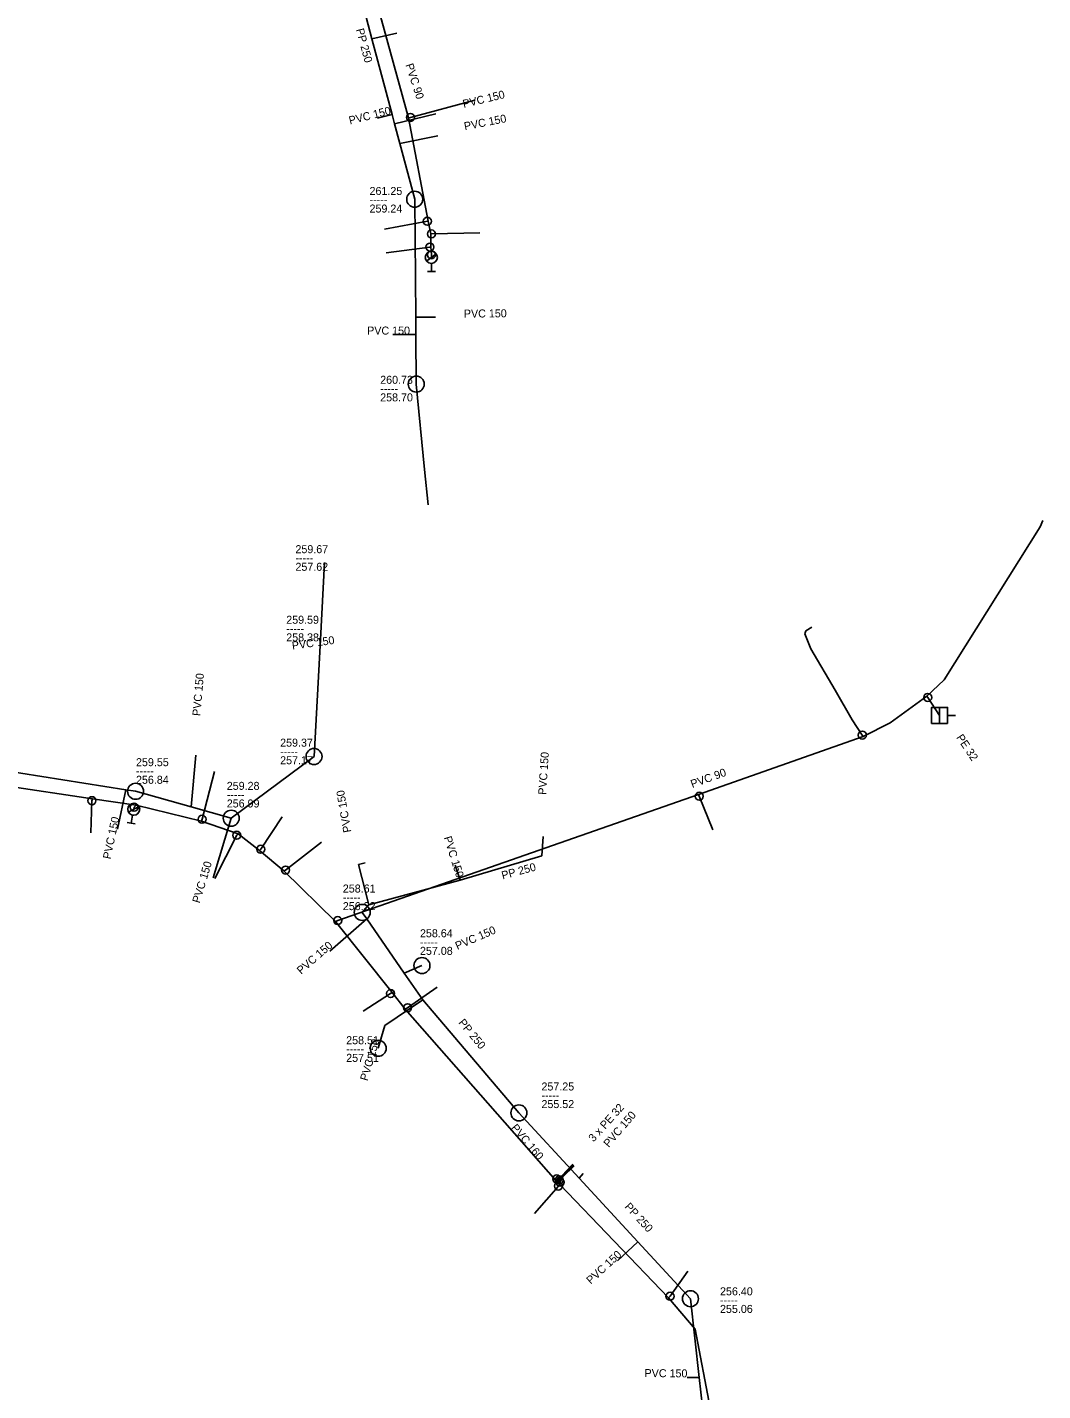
# Model space of a CAD drawing. Extents: x -770828 to -770111, y -1050344 to -1049447.
# Drawn here: x -770523.9 to -770397, y -1050086.5 to -1049916.1 of the extents above; entities that cross this region are included whole.
import ezdxf

# ---------------------------------------------------------------- set-up
doc = ezdxf.new("R2010")
doc.units = 0
doc.layers.add('Level 0', color=7, linetype='Continuous')

msp = doc.modelspace()

# ---------------------------------------------------------------- linework, layer by layer
at = {"layer": 'Level 0'}
for p, q in [((-770484.57, -1049903.39), (-770480.8, -1049917.54)), ((-770479.95, -1049913.96), (-770476.22, -1049927.41)), ((-770480.8, -1049917.54), (-770477.68, -1049916.84)), ((-770480.8, -1049917.54), (-770478.28, -1049926.99)), ((-770476, -1049927.35), (-770467.95, -1049925.2)), ((-770478.28, -1049926.99), (-770480.12, -1049927.45)), ((-770478.28, -1049926.99), (-770477.97, -1049928.16)), ((-770477.97, -1049928.16), (-770472.82, -1049926.92)), ((-770477.97, -1049928.16), (-770477.32, -1049930.6)), ((-770476.22, -1049927.41), (-770476, -1049927.35)), ((-770476.22, -1049927.41), (-770473.78, -1049940.31)), ((-770477.32, -1049930.6), (-770472.58, -1049929.67)), ((-770477.32, -1049930.6), (-770475.46, -1049937.58)), ((-770475.46, -1049937.58), (-770475.33, -1049952.33)), ((-770473.88, -1049940.33), (-770479.24, -1049941.32)), ((-770473.78, -1049940.31), (-770473.88, -1049940.33)), ((-770473.78, -1049940.31), (-770473.46, -1049941.91)), ((-770473.36, -1049941.91), (-770467.3, -1049941.76)), ((-770473.55, -1049943.55), (-770479.04, -1049944.26)), ((-770473.45, -1049943.54), (-770473.55, -1049943.55)), ((-770473.46, -1049941.91), (-770473.36, -1049941.91)), ((-770473.46, -1049941.91), (-770473.45, -1049943.54)), ((-770473.45, -1049943.54), (-770473.37, -1049944.52)), ((-770472.79, -1049944.38), (-770473.97, -1049945.3)), ((-770473.37, -1049944.52), (-770473.38, -1049944.84)), ((-770472.88, -1049946.59), (-770473.88, -1049946.59)), ((-770473.38, -1049945.59), (-770473.38, -1049946.59)), ((-770475.33, -1049952.33), (-770472.88, -1049952.31)), ((-770475.33, -1049952.33), (-770475.31, -1049954.49)), ((-770475.31, -1049954.49), (-770478.18, -1049954.48)), ((-770475.31, -1049954.49), (-770475.26, -1049960.68)), ((-770475.26, -1049960.68), (-770474.22, -1049971.34)), ((-770474.22, -1049971.34), (-770473.78, -1049975.77)), ((-770409.32, -1049997.65), (-770397.32, -1049978.5)), ((-770397.32, -1049978.5), (-770396.99, -1049977.74)), ((-770486.71, -1049982.98), (-770487.24, -1049992.58)), ((-770426.57, -1049991.52), (-770425.85, -1049991.06)), ((-770487.24, -1049992.58), (-770488.04, -1050007.22)), ((-770426.7, -1049991.91), (-770426.57, -1049991.52)), ((-770425.98, -1049993.75), (-770426.7, -1049991.91)), ((-770422.94, -1049998.93), (-770425.98, -1049993.75)), ((-770411.47, -1049999.68), (-770409.32, -1049997.65)), ((-770420.8, -1050002.64), (-770422.94, -1049998.93)), ((-770416.05, -1050003.03), (-770411.47, -1049999.68)), ((-770411.47, -1049999.68), (-770411.36, -1049999.84)), ((-770411.36, -1049999.84), (-770409.88, -1050002.09)), ((-770419.53, -1050004.55), (-770420.8, -1050002.64)), ((-770419.42, -1050004.71), (-770416.05, -1050003.03)), ((-770407.88, -1050002.09), (-770408.88, -1050002.09)), ((-770439.99, -1050011.95), (-770419.42, -1050004.71)), ((-770419.42, -1050004.71), (-770419.53, -1050004.55)), ((-770503.39, -1050013.52), (-770502.82, -1050007.04)), ((-770488.04, -1050007.22), (-770498.38, -1050014.93)), ((-770511.54, -1050011.38), (-770527.35, -1050008.9)), ((-770502.02, -1050015.07), (-770500.48, -1050009.1)), ((-770515.73, -1050012.51), (-770526.84, -1050010.84)), ((-770511.54, -1050011.38), (-770512.58, -1050016.3)), ((-770510.33, -1050011.57), (-770511.54, -1050011.38)), ((-770503.39, -1050013.52), (-770510.33, -1050011.57)), ((-770515.79, -1050012.74), (-770515.93, -1050016.74)), ((-770515.73, -1050012.51), (-770515.79, -1050012.74)), ((-770510.25, -1050013.31), (-770515.73, -1050012.51)), ((-770510.25, -1050013.31), (-770510.51, -1050013.57)), ((-770502.11, -1050015.29), (-770510.25, -1050013.31)), ((-770485.07, -1050027.72), (-770439.99, -1050011.95)), ((-770439.99, -1050011.95), (-770439.9, -1050012.18)), ((-770439.9, -1050012.18), (-770438.22, -1050016.37)), ((-770509.91, -1050013.47), (-770511.23, -1050014.17)), ((-770510.7, -1050014.56), (-770510.87, -1050015.54)), ((-770510.51, -1050013.57), (-770510.57, -1050013.82)), ((-770498.38, -1050014.93), (-770503.39, -1050013.52)), ((-770502.11, -1050015.29), (-770502.02, -1050015.07)), ((-770498.38, -1050014.93), (-770500.64, -1050022.4)), ((-770494.7, -1050018.81), (-770492.01, -1050014.75)), ((-770510.38, -1050015.63), (-770511.37, -1050015.46)), ((-770497.52, -1050016.87), (-770502.11, -1050015.29)), ((-770497.52, -1050016.87), (-770497.69, -1050017.06)), ((-770494.87, -1050018.98), (-770497.52, -1050016.87)), ((-770497.69, -1050017.06), (-770500.44, -1050022.47)), ((-770491.59, -1050021.41), (-770487.11, -1050017.91)), ((-770459.58, -1050019.64), (-770459.42, -1050017.2)), ((-770494.87, -1050018.98), (-770494.7, -1050018.81)), ((-770491.81, -1050021.52), (-770494.87, -1050018.98)), ((-770459.58, -1050019.64), (-770469.79, -1050022.69)), ((-770491.81, -1050021.52), (-770491.59, -1050021.41)), ((-770485.35, -1050027.84), (-770491.81, -1050021.52)), ((-770482.46, -1050020.71), (-770481.65, -1050020.53)), ((-770481.2, -1050025.77), (-770482.46, -1050020.71)), ((-770469.79, -1050022.69), (-770470.39, -1050020.79)), ((-770469.79, -1050022.69), (-770481.2, -1050025.77)), ((-770481.2, -1050025.77), (-770482.01, -1050026.7)), ((-770482.01, -1050026.7), (-770481.45, -1050027.51)), ((-770481.45, -1050027.51), (-770486.07, -1050031.56)), ((-770485.35, -1050027.84), (-770485.07, -1050027.72)), ((-770478.29, -1050036.71), (-770485.35, -1050027.84)), ((-770481.45, -1050027.51), (-770476.76, -1050034.31)), ((-770476.76, -1050034.31), (-770474.55, -1050033.35)), ((-770476.76, -1050034.31), (-770474.43, -1050037.65)), ((-770478.48, -1050036.84), (-770481.88, -1050039.06)), ((-770478.29, -1050036.71), (-770478.48, -1050036.84)), ((-770476.63, -1050038.81), (-770478.29, -1050036.71)), ((-770476.35, -1050038.62), (-770472.67, -1050036.03)), ((-770474.43, -1050037.65), (-770479.17, -1050040.83)), ((-770476.63, -1050038.81), (-770476.35, -1050038.62)), ((-770457.82, -1050060.22), (-770476.63, -1050038.81)), ((-770474.43, -1050037.65), (-770462.44, -1050051.76)), ((-770479.17, -1050040.83), (-770480.02, -1050043.69)), ((-770462.44, -1050051.76), (-770454.92, -1050059.91)), ((-770455.72, -1050058.18), (-770457.1, -1050059.66)), ((-770457.03, -1050059.72), (-770455.62, -1050058.27)), ((-770455.52, -1050058.36), (-770456.98, -1050059.79)), ((-770454.92, -1050059.91), (-770454.42, -1050059.33)), ((-770457.5, -1050060.91), (-770460.5, -1050064.32)), ((-770457.71, -1050060.01), (-770457.82, -1050060.22)), ((-770457.67, -1050060.34), (-770457.82, -1050060.22)), ((-770457.1, -1050059.66), (-770457.71, -1050060.01)), ((-770457.67, -1050060.34), (-770457.4, -1050060.13)), ((-770457.47, -1050060.55), (-770457.67, -1050060.34)), ((-770457.32, -1050060.7), (-770457.5, -1050060.91)), ((-770457.29, -1050060.42), (-770457.47, -1050060.55)), ((-770457.32, -1050060.7), (-770457.47, -1050060.55)), ((-770457.4, -1050060.13), (-770457.03, -1050059.72)), ((-770443.76, -1050074.87), (-770457.32, -1050060.7)), ((-770456.98, -1050059.79), (-770457.29, -1050060.42)), ((-770454.92, -1050059.91), (-770447.56, -1050067.88)), ((-770447.56, -1050067.88), (-770450.11, -1050070.24)), ((-770447.56, -1050067.88), (-770441, -1050074.98)), ((-770443.56, -1050074.68), (-770441.32, -1050071.54)), ((-770443.76, -1050074.87), (-770443.56, -1050074.68)), ((-770440.42, -1050078.8), (-770443.76, -1050074.87)), ((-770441, -1050074.98), (-770439.91, -1050084.82)), ((-770438.53, -1050088.64), (-770440.42, -1050078.8)), ((-770439.91, -1050084.82), (-770441.4, -1050084.81)), ((-770439.91, -1050084.82), (-770439.09, -1050092.2))]:
    msp.add_line(p, q, dxfattribs=at)
msp.add_lwpolyline([(-770409.88, -1050003.09), (-770410.88, -1050003.09), (-770410.88, -1050001.09), (-770409.88, -1050001.09)], dxfattribs=at)
msp.add_lwpolyline([(-770408.88, -1050003.09), (-770408.88, -1050001.09), (-770409.88, -1050001.09), (-770409.88, -1050003.09)], close=True, dxfattribs=at)
for centre, radius in [((-770476, -1049927.35), 0.5), ((-770475.46, -1049937.58), 1), ((-770473.88, -1049940.33), 0.5), ((-770473.36, -1049941.91), 0.5), ((-770473.55, -1049943.55), 0.5), ((-770473.38, -1049944.84), 0.75), ((-770473.37, -1049944.52), 0.5), ((-770475.26, -1049960.68), 1), ((-770411.36, -1049999.84), 0.5), ((-770419.53, -1050004.55), 0.5), ((-770488.04, -1050007.22), 1), ((-770510.33, -1050011.57), 1), ((-770439.9, -1050012.18), 0.5), ((-770515.79, -1050012.74), 0.5), ((-770510.57, -1050013.82), 0.75), ((-770510.51, -1050013.57), 0.5), ((-770502.02, -1050015.07), 0.5), ((-770498.38, -1050014.93), 1), ((-770497.69, -1050017.06), 0.5), ((-770494.7, -1050018.81), 0.5), ((-770491.59, -1050021.41), 0.5), ((-770482.01, -1050026.7), 1), ((-770485.07, -1050027.72), 0.5), ((-770474.55, -1050033.35), 1), ((-770478.48, -1050036.84), 0.5), ((-770476.35, -1050038.62), 0.5), ((-770480.02, -1050043.69), 1), ((-770462.44, -1050051.76), 1), ((-770457.71, -1050060.01), 0.5), ((-770457.5, -1050060.91), 0.5), ((-770457.4, -1050060.13), 0.5), ((-770457.29, -1050060.42), 0.5), ((-770443.56, -1050074.68), 0.5), ((-770441, -1050074.98), 1)]:
    msp.add_circle(centre, radius, dxfattribs=at)

# ---------------------------------------------------------------- texts
for s, rotation, p in [('PP 250', 284.84, (-770482.8, -1049916.36)), ('PVC 90', 287.819, (-770476.62, -1049920.78)), ('PVC 150', 13.538, (-770469.33, -1049926.17)), ('PVC 150', 14.036, (-770483.55, -1049928.24)), ('PVC 150', 11.101, (-770469.19, -1049928.96)), ('PVC 150', 0.468, (-770469.31, -1049952.37)), ('PVC 150', 359.8, (-770481.4, -1049954.48)), ('PVC 150', 7.843, (-770490.73, -1049993.87)), ('PVC 150', 84.973, (-770502.25, -1050002.19)), ('PE 32', 303.336, (-770407.83, -1050004.84)), ('PVC 150', 86.248, (-770459.04, -1050012.03)), ('PVC 90', 20, (-770440.77, -1050011.17)), ('PVC 150', 99.837, (-770483.37, -1050016.64)), ('PVC 150', 78.064, (-770513.46, -1050020.11)), ('PVC 150', 287.526, (-770471.84, -1050017.35)), ('PVC 150', 73.167, (-770502.33, -1050025.62)), ('PP 250', 15.106, (-770464.46, -1050022.59)), ('PVC 150', 23.48, (-770470.13, -1050031.4)), ('PVC 150', 41.239, (-770489.65, -1050034.5)), ('PP 250', 309.369, (-770470.05, -1050040.51)), ('PVC 150', 73.448, (-770481.36, -1050047.83)), ('3 x PE 32', 47.936, (-770453.11, -1050055.46)), ('PVC 150', 49.236, (-770451.22, -1050056.14)), ('PVC 160', 310.36, (-770463.48, -1050053.67)), ('PP 250', 312.721, (-770449.3, -1050063.55)), ('PVC 150', 42.784, (-770453.45, -1050073.23)), ('PVC 150', 359.615, (-770446.74, -1050084.78))]:
    msp.add_text(s, height=1, rotation=rotation, dxfattribs=at).set_placement(p)
for s, p in [('261.25', (-770481.1, -1049937.04)), ('-----', (-770481.1, -1049938.14)), ('259.24', (-770481.1, -1049939.24)), ('260.73', (-770479.77, -1049960.64)), ('-----', (-770479.77, -1049961.74)), ('258.70', (-770479.77, -1049962.84)), ('259.67', (-770490.36, -1049981.81)), ('-----', (-770490.36, -1049982.91)), ('257.62', (-770490.36, -1049984.01)), ('-----', (-770491.51, -1049991.73)), ('259.59', (-770491.51, -1049990.63)), ('258.38', (-770491.51, -1049992.83)), ('-----', (-770492.27, -1050007.09)), ('259.37', (-770492.27, -1050005.99)), ('259.55', (-770510.28, -1050008.43)), ('257.17', (-770492.27, -1050008.19)), ('-----', (-770510.28, -1050009.53)), ('256.84', (-770510.28, -1050010.63)), ('259.28', (-770498.94, -1050011.39)), ('-----', (-770498.94, -1050012.49)), ('256.99', (-770498.94, -1050013.59)), ('258.61', (-770484.44, -1050024.22)), ('-----', (-770484.44, -1050025.32)), ('256.32', (-770484.44, -1050026.42)), ('258.64', (-770474.8, -1050029.81)), ('-----', (-770474.8, -1050030.91)), ('257.08', (-770474.8, -1050032.01)), ('258.51', (-770484.02, -1050043.18)), ('-----', (-770484.02, -1050044.28)), ('257.51', (-770484.02, -1050045.38)), ('257.25', (-770459.62, -1050048.96)), ('-----', (-770459.62, -1050050.06)), ('255.52', (-770459.62, -1050051.16)), ('256.40', (-770437.31, -1050074.56)), ('-----', (-770437.31, -1050075.66)), ('255.06', (-770437.31, -1050076.76))]:
    msp.add_text(s, height=1, dxfattribs=at).set_placement(p)

doc.saveas('drawing.dxf')
